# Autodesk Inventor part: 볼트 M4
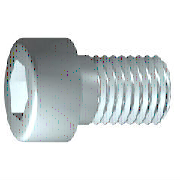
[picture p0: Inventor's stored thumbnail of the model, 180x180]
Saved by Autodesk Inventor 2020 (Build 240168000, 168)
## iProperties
IsCustomPart: 0
Created: 2012-02
Part Number: 볼트 M4
Material: 스테인리스강
Description: 6각 소켓 머리 캡 나사
Document SubType Name: Modeling
Standard: ISO 4762
Designer: mduedu
Standard Revision: Fourth edition 2004-03-01
Standards Organization: ISO
Language: ko-KR
Size Designation: M4 x 12
Categories: <MemberInstance><Categories><Category DisplayName="조임쇠" InternalName="e4da775c-781d-43d5-af7c-5136215cf5a6" Mnemonic="FSTN"><Category DisplayName="볼트" InternalN
Density: 8.08 g/cm^3
Mass: 2.2972 g
Surface Area: 3.30853 cm^2
Volume: 0.284306 cm^3
Appearance: 반광택
Author: mduedu
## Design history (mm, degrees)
sketch "스케치1"
  geometry: L1 (-1, 0)-(12, 0); L2 (12, 0)-(12, 2); L3 (12, 2)-(1.75, 2); L4 (1.75, 2)-(1.32, 2); L5 (1.32, 2)-(0, 2); L6 (0, 2)-(0, 3.5); L7 (0, 3.5)-(-4, 3.5); L8 (-4, 3.5)-(-4, 1.732); L9 (-4, 1.732)-(-2, 1.732); L10 (-2, 1.732)-(-1, 0); L11 (-7.2, 0)-(15.2, 0) reference; L12 (0, -0.7)-(0, 4.2) reference; L13 (1.75, 2)-(0, 2)
  constraints: 22 end point, 6 parallel, 2 collinear, 2 perpendicular, 1 horizontal, 1 point on line
  dimensions: "d1" = 10.25 distance from line of L3.end L2 (= GEL); "d2" = 0.42952 distance of L4.end L3.end (computed from GAL); "d3" = 4 distance between parallel lines of L8 L6 (= KOH); "d4" = 2 distance of L8.end L9.end (= INTI); "d5" = 60 deg angle of L10 L1; "d6" = 4 diameter of L3 L1 (= GD); "d7" = 4 diameter of L5 L1 (= BDM); "d8" = 3.4641 diameter of L9 L1 (= 1.1547 x SW); "d9" = 7 diameter of L7 L1 (= KOD); "d26" = 12 distance between parallel lines of L12 L2 (= NLG)
revolve "본체" sketch "스케치1" stored, may be unused: angle "d10" = 90 deg
sketch "스케치2"
  geometry: L1 (0, -4.9)-(0, 4.9) reference; L2 (-4.9, 0)-(4.9, 0) reference; L3 (1.732, 0)-(0.866, -1.5); L4 (0.866, -1.5)-(-0.866, -1.5); L5 (-0.866, -1.5)-(-1.732, 0); L6 (-1.732, 0)-(-0.866, 1.5); L7 (-0.866, 1.5)-(0.866, 1.5); L8 (0.866, 1.5)-(1.732, 0); 2 further points
  constraints: 12 end point, 1 coincident, 1 horizontal alignment, 1 point on line, 12 other
extrude "슬롯" join sketch "스케치2" stored distance "d11" = 10; taper "d12" = 0 deg
workplane "Work Plane1"
fillet "Fillet2" dims "d30" = 0.1 (= R)
body "Solid1"
fillet "모깎기1" dims "d17" = 0.4 (= RR)
feature "스레드" dims "d13" = 10.25 (= GEL), "d14" = 0
chamfer "모따기1" distance "d15" = 0.42941 (= -0.5 x SPD + 0.5 x GD); stored, may be unused: second distance "d16" = 0.42941 (= GUL), angle "d27" = 45 deg
other parameters: "GD" = 4 [user parameter; used in 2 equation terms], "NLG" = 12 [user parameter; used in 1 equation term], "GEL" = 10.25 [user parameter; used in 2 equation terms], "KOD" = 7 [user parameter; used in 1 equation term], "KOH" = 4 [user parameter; used in 1 equation term], "INTI" = 2 [user parameter; used in 1 equation term], "GAL" = 0.42941 (= 0.61345 x PTC) [user parameter; used in 1 equation term], "GUL" = 0.42941 (= 0.61345 x PTC) [user parameter; used in 1 equation term], "BDM" = 4 (= NND) [user parameter; used in 1 equation term], "SW" = 3 [user parameter; used in 2 equation terms], "RR" = 0.4 [user parameter; used in 1 equation term], "SPD" = 3.14117 (= NND - 1.2269 x PTC) [user parameter; used in 1 equation term], "d19" = 0, "d28" = 0, "d29" = 0, "R" = 0.1 [user parameter; used in 1 equation term], "TOA" = 30 deg [user parameter], "GD1" = 3.14117 (= THREADDIA - 1.2269 x PTC) [user parameter], "THREADDIA" = 4 [user parameter; used in 1 equation term], "FAWI" = 45 deg [user parameter], "TPU" = 14.28571 (computed from PTC) [user parameter], "PTC" = 0.7 [user parameter; used in 5 equation terms], "NND" = 4 [user parameter; used in 2 equation terms], "E0" = 3.465 (= 1.155 x SW) [user parameter]
